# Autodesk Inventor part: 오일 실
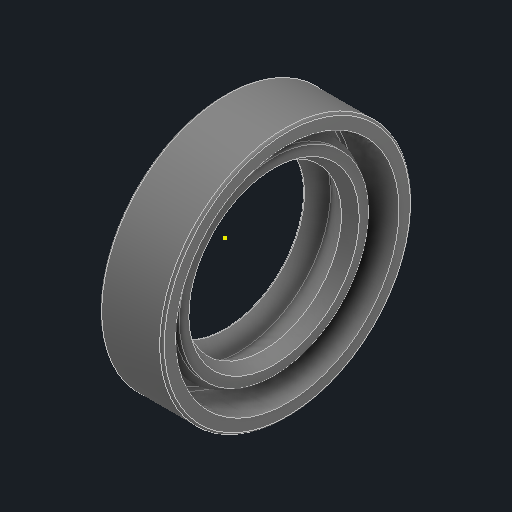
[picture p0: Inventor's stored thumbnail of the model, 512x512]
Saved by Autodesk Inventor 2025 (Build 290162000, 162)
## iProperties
Created: 2025-08
Part Number: 오일 실
Material: 고무
Description: 오일-실
Document SubType Name: Modeling
Designer: infra012
Density: 0.93 g/cm^3
Appearance: 기본값
Author: jhkim
Sending System: Autodesk Inventor 2026
Preprocessor: ST-DEVELOPER v20.1
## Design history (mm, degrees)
sketch "스케치1"
  geometry: 1 further point
  constraints: 1 other
feature "Solid1"
node "솔리드1"
